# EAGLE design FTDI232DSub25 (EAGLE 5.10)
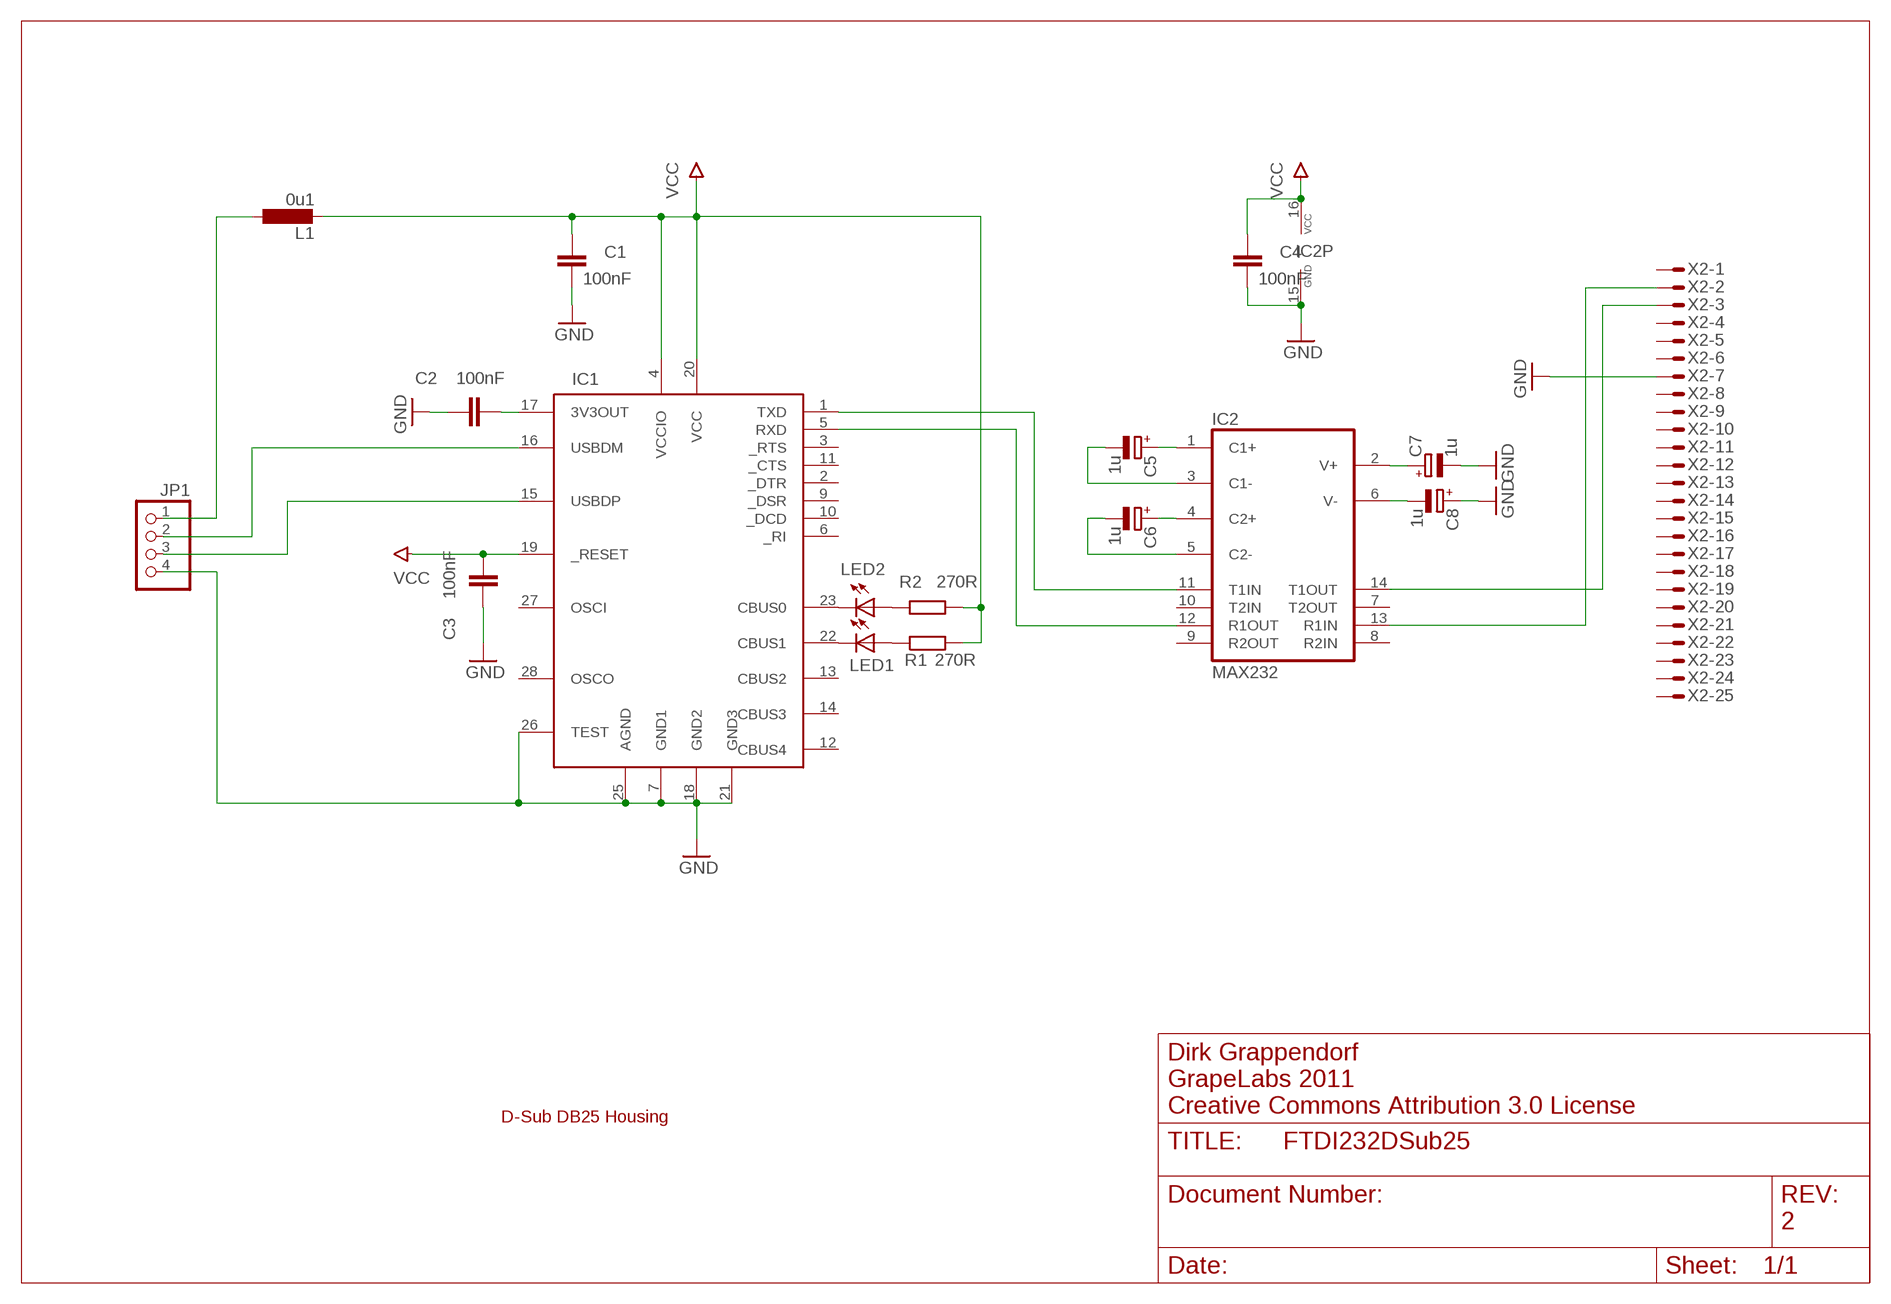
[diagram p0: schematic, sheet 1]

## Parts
C1  100nF  C-EUC1206  [C1206]
C2  100nF  C-EUC1206  [C1206]
C3  100nF  C-EUC1206  [C1206]
C4  100nF  C-EUC1206  [C1206]
C5  1u  CPOL-EUB  [PANASONIC_B]
C6  1u  CPOL-EUB  [PANASONIC_B]
C7  1u  CPOL-EUB  [PANASONIC_B]
C8  1u  CPOL-EUB  [PANASONIC_B]
IC1  FT232RL  [SSOP28DB]
IC2  MAX232  [DIL16]
JP1  PINHD-1X4  [1X04]
L1  0u1  L-EUL2825P  [L2825P]
LED1  LED3MM  [LED3MM]
LED2  LED3MM  [LED3MM]
R1  270R  R-EU_M1206  [M1206]
R2  270R  R-EU_M1206  [M1206]
U$1  DSUB25-HOUSING  [DSUB25-HOUSING]
X2  M25DS  [M25D]

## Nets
GND: C1.2 C2.1 C3.1 C4.2 C7.- C8.+ IC1.7(GND1) IC1.18(GND2) IC1.21(GND3) IC1.25(AGND) IC1.26(TEST) IC2.15(GND) JP1.4 X2.7
N$1: C2.2 IC1.17(3V3OUT)
N$2: JP1.1 L1.1
N$3: IC1.15(USBDP) JP1.3
N$4: IC1.16(USBDM) JP1.2
N$5: LED1.A R1.1
N$6: LED2.A R2.1
N$7: IC1.22(CBUS1) LED1.K(C)
N$8: IC1.23(CBUS0) LED2.K(C)
N$11: C5.+ IC2.1(C1+)
N$12: C5.- IC2.3(C1-)
N$13: C6.+ IC2.4(C2+)
N$14: C6.- IC2.5(C2-)
N$15: C7.+ IC2.2(V+)
N$16: C8.- IC2.6(V-)
N$17: IC1.1(TXD) IC2.11(T1IN)
N$18: IC2.14(T1OUT) X2.3
N$19: IC2.13(R1IN) X2.2
N$20: IC1.5(RXD) IC2.12(R1OUT)
VCC: C1.1 C3.2 C4.1 IC1.4(VCCIO) IC1.19(_RESET) IC1.20(VCC) IC2.16(VCC) L1.2 R1.2 R2.2
Unconnected: IC1.2(_DTR) IC1.3(_RTS) IC1.6(_RI) IC1.9(_DSR) IC1.10(_DCD) IC1.11(_CTS) IC1.12(CBUS4) IC1.13(CBUS2) IC1.14(CBUS3) IC1.27(OSCI) IC1.28(OSCO) IC2.7(T2OUT) IC2.8(R2IN) IC2.9(R2OUT) IC2.10(T2IN) X2.1 X2.4 X2.5 X2.6 X2.8 X2.9 X2.10 X2.11 X2.12 X2.13 X2.14 X2.15 X2.16 X2.17 X2.18 X2.19 X2.20 X2.21 X2.22 X2.23 X2.24 X2.25

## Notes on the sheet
- TxD
- RxD
- Clk6
- Clk12
- Dirk Grappendorf
- GrapeLabs 2011
- Creative Commons Attribution 3.0 License
- 2

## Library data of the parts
C1-C4 = rcl:C-EU: CAPACITOR, European symbol
C5-C8 = rcl:CPOL-EU: POLARIZED CAPACITOR, European symbol
IC1 = ftdichip:FT232RL: USB UART 4th Generation USB UART (USB <-> Serial) Controller
IC2 = maxim:MAX232: RS232 TRANSEIVER
JP1 = pinhead:PINHD-1X4: PIN HEADER
L1 = rcl:L-EU: INDUCTOR, European symbol
LED1 LED2 = led:LED: LED
R1 R2 = rcl:R-EU_: RESISTOR, European symbol
U$1 = grapelabs:DSUB25-HOUSING: Passend für 25pol D-Sub Steckergehäuse
X2 = con-subd:M25?S: SUB-D

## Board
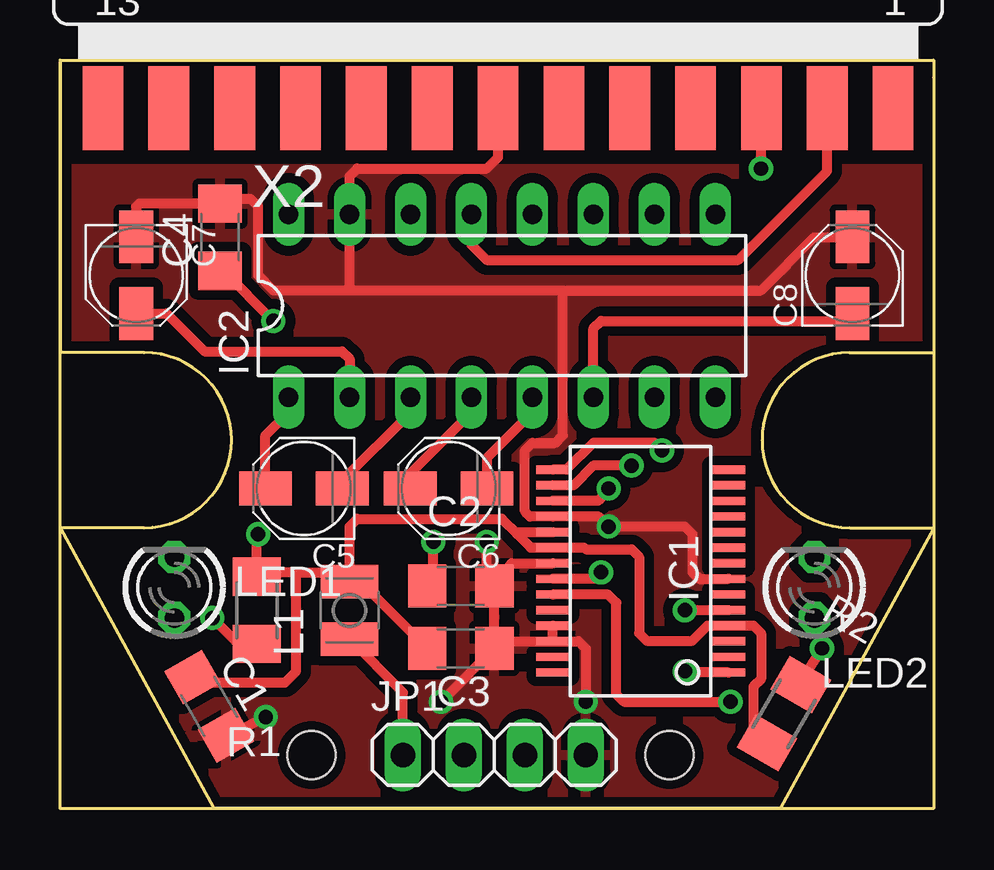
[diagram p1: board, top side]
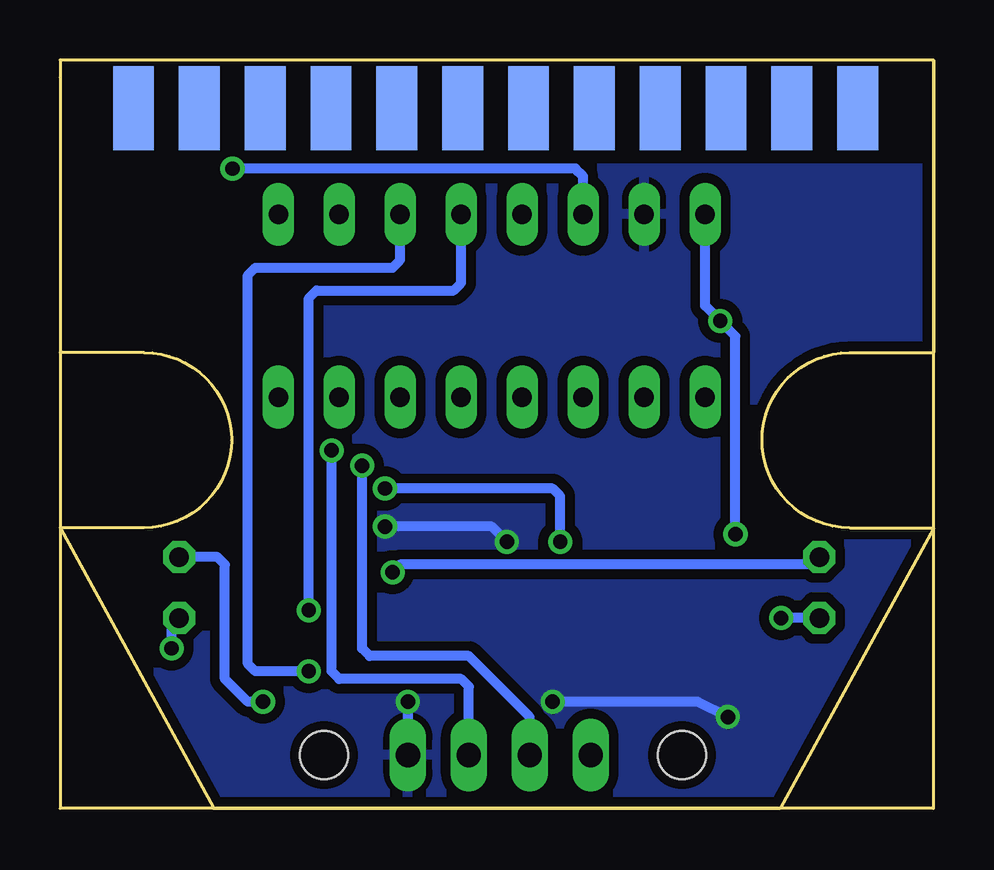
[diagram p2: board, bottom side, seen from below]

Size 36.4 x 31.2 mm. Coordinates in mm from the lower left corner, seen from the top.
Outline: 0,31.11 0,0 36.4,0 36.4,30.48
Copper layers (1*16): Top 0.035mm / dielectric 1.5mm / Bottom 0.035mm
Design rules "default *": minimum track width 10mil, minimum drill 16mil, track to track 8mil, track to pad 8mil, pad to pad 8mil, via to via 8mil, smd to smd 8mil, copper to edge 16mil, drill to drill 10mil, minimum pad ring 10mil, minimum via ring 8mil, stop-mask expansion 4mil, vias tented up to drill 0mil, thermal gap 10mil
Holes 2 mm at 10.48,2.22 25.4,2.22

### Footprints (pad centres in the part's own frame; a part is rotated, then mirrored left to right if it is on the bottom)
C1206 = smd 1.6 x 1.8: 1 -1.4,0; 2 1.4,0
PANASONIC_B = smd 2.2 x 1.4: + 1.6,0; - -1.6,0
SSOP28DB = smd 0.348 x 1.397: 1 -4.225,-3.656; 2 -3.575,-3.656; 3 -2.925,-3.656; 4 -2.275,-3.656; 5 -1.625,-3.656; 6 -0.975,-3.656; 7 -0.325,-3.656; 8 0.325,-3.656; 9 0.975,-3.656; 10 1.625,-3.656; 11 2.275,-3.656; 12 2.925,-3.656; 13 3.575,-3.656; 14 4.225,-3.656; 15 4.225,3.656; 16 3.575,3.656; 17 2.925,3.656; 18 2.275,3.656; 19 1.625,3.656; 20 0.975,3.656; 21 0.325,3.656; 22 -0.325,3.656; 23 -0.975,3.656; 24 -1.625,3.656; 25 -2.275,3.656; 26 -2.925,3.656; 27 -3.575,3.656; 28 -4.225,3.656
DIL16 = drill 0.813 long: 1 -8.89,-3.81; 2 -6.35,-3.81; 3 -3.81,-3.81; 4 -1.27,-3.81; 5 1.27,-3.81; 6 3.81,-3.81; 7 6.35,-3.81; 8 8.89,-3.81; 9 8.89,3.81; 10 6.35,3.81; 11 3.81,3.81; 12 1.27,3.81; 13 -1.27,3.81; 14 -3.81,3.81; 15 -6.35,3.81; 16 -8.89,3.81
1X04 = drill 1.016 long: 1 -3.81,0; 2 -1.27,0; 3 1.27,0; 4 3.81,0
L2825P = smd 1.4 x 2.4: 1 -1.2,0; 2 1.2,0
LED3MM = drill 0.813 octagon: A -1.27,0; K 1.27,0
M1206 = smd 1.6 x 2: 1 -1.4,0; 2 1.4,0
M25D = smd 1.7 x 3.5: 1 16.459,-6.045; 2 13.716,-6.045; 3 10.973,-6.045; 4 8.23,-6.045; 5 5.486,-6.045; 6 2.743,-6.045; 7 0,-6.045; 8 -2.743,-6.045; 9 -5.486,-6.045; 10 -8.23,-6.045; 11 -10.973,-6.045; 12 -13.716,-6.045; 13 -16.459,-6.045 | smd 1.7 x 3.5 bottom: 14 15.088,-6.045; 15 12.344,-6.045; 16 9.601,-6.045; 17 6.858,-6.045; 18 4.115,-6.045; 19 1.372,-6.045; 20 -1.372,-6.045; 21 -4.115,-6.045; 22 -6.858,-6.045; 23 -9.601,-6.045; 24 -12.344,-6.045; 25 -15.088,-6.045

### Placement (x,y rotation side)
C1  6.22,4.26 300 top
C2  16.7,9.27 180 top
C3  16.7,6.67 180 top
C4  6.67,23.81 90 top
C5  10.16,13.34 180 top
C6  16.19,13.34 180 top
C7  3.17,22.23 270 top
C8  33.02,22.23 90 top
IC1  24.19,9.89 90 top
IC2  18.41,20.95 0 top
JP1  18.1,2.22 0 top
L1  12.06,8.26 90 top
LED1  4.76,9.21 90 top
LED2  31.43,9.21 90 top
R1  8.21,8.26 90 top
R2  30.16,3.94 240 top
U$1  0,0 0 top
X2  18.25,35.23 0 top

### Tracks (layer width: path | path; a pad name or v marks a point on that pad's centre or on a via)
GND  (via drill 0.6)
  Top 0.406: IC1.21 18.81,10.22 C2.1 | C7.- 3.17,25.08 3.31,25.21 C4.2 6.86,25.4 7.94,25.4 8.26,25.08 8.26,22.23 8.89,21.59 12.06,21.59 | 20.95,21.59 12.06,21.59 | 20.95,21.59 29.21,21.59 31.43,23.81 33.01,23.81 C8.+ | 20.95,21.59 20.95,15.56 20.64,15.24 19.68,15.24 19.37,14.92 19.37,12.38 19.58,12.17 IC1.18 22.44,12.17 v22.86,11.75 26.04,11.75 26.35,11.43 26.35,9.84 26.63,9.57 IC1.7 | 12.06,21.59 IC2.15 12.06,26.35 12.38,26.67 17.78,26.67 18.25,27.14 X2.7 | C3.1 C2.1 | IC1.26 21.61,6.97 21.91,6.67 v21.91,4.45 | IC1.26 IC1.25 | IC1.26 18.4,6.97 C3.1 | C3.1 v15.88,4.45 | v8.57,3.81 7.3,3.17 6.73,2.86 C1.2 | v17.78,11.11 17.78,9.59 C2.1
  Bottom 0.406: v21.91,4.45 JP1.4 | v15.88,4.45 9.84,4.45 v8.57,3.81 | v22.86,11.75 18.41,11.75 v17.78,11.11
  pour Top (isolate 0.406): -1.27,-1.27 -1.27,26.67 37.47,26.67 37.47,-1.27
  pour Bottom (isolate 0.406): -1.27,-1.27 -1.27,26.67 37.47,26.67 37.47,-1.27
N$1  (via drill 0.6)
  Top 0.406: IC1.17 22.43,12.82 v22.86,13.34 | v15.56,11.11 15.56,9.53 C2.2
  Bottom 0.406: v22.86,13.34 15.88,13.34 15.56,13.02 v15.56,11.11
N$2
  Top 0.406: JP1.1 14.29,4.83 L1.1
N$3  (via drill 0.6)
  Top 0.406: IC1.15 21.1,14.12 22.23,15.24 24.77,15.24 v25.08,14.92
  Bottom 0.406: v25.08,14.92 25.08,5.71 24.77,5.4 19.68,5.4 19.37,5.08 JP1.3
N$4  (via drill 0.6)
  Top 0.406: IC1.16 21.41,13.47 22.23,14.29 v23.81,14.29
  Bottom 0.406: v23.81,14.29 23.81,6.67 23.5,6.35 19.37,6.35 16.83,3.81 JP1.2
N$5  (via drill 0.6)
  Top 0.406: R1.1 7.43,6.86 v6.35,7.94
  Bottom 0.406: LED1.A v6.35,7.94
N$6  (via drill 0.6)
  Top 0.406: R2.1 31.18,5.78 v31.75,6.67
  Bottom 0.406: v31.75,6.67 31.75,7.62 LED2.A
N$7  (via drill 0.6)
  Top 0.406: IC1.22 22.27,9.57 v22.54,9.84
  Bottom 0.406: v22.54,9.84 22.23,10.16 5.08,10.16 LED1.K
N$8  (via drill 0.6)
  Top 0.406: IC1.23 22.83,8.92 23.18,8.57 23.18,4.76 23.5,4.45 v27.94,4.45
  Bottom 0.406: v27.94,4.45 28.57,4.45 29.53,5.4 29.53,10.16 29.84,10.48 LED2.K
N$11
  Top 0.406: C5.+ 8.56,15.54 9.53,16.51 IC2.1
N$12
  Top 0.406: C5.- 11.76,13.66 14.61,16.51 IC2.3
N$13
  Top 0.406: C6.+ 14.59,13.96 17.14,16.51 IC2.4
N$14
  Top 0.406: C6.- 17.79,14.62 19.68,16.51 IC2.5
N$15
  Top 0.406: IC2.2 12.06,18.73 11.75,19.05 6.03,19.05 4.45,20.64 3.19,20.64 C7.+
N$16
  Top 0.406: IC2.6 22.23,20 22.54,20.32 32.72,20.32 C8.-
N$17  (via drill 0.6)
  Top 0.406: IC1.1 26.4,5.67 v26.04,5.71
  Bottom 0.406: v26.04,5.71 28.26,5.71 28.57,6.03 28.57,22.23 28.26,22.54 22.54,22.54 22.23,22.86 IC2.11
N$18  (via drill 0.6)
  Top 0.406: v29.21,26.67 29.21,29.17 X2.3
  Bottom 0.406: IC2.14 14.61,26.35 14.92,26.67 v29.21,26.67
N$19
  Top 0.406: IC2.13 17.14,23.5 17.78,22.86 28.26,22.86 31.97,26.57 X2.2
N$20  (via drill 0.6)
  Top 0.406: v26.04,8.26 27.84,8.26 IC1.5
  Bottom 0.406: IC2.12 19.68,21.91 20,21.59 25.72,21.59 26.04,21.27 v26.04,8.26
VCC  (via drill 0.6)
  Top 0.406: 19.05,11.43 18.41,12.06 12.38,12.06 12.06,11.75 L1.2 | 19.05,11.43 19.61,10.87 IC1.20 21.84,10.87 21.91,10.79 23.81,10.79 24.13,10.48 24.13,7.3 24.45,6.99 26.35,6.99 26.99,7.62 IC1.4 28.89,7.62 29.21,7.3 29.21,5.4 28.89,5.08 28.89,3.3 R2.2 29.21,3.3 | IC1.19 19.14,11.52 19.05,11.43 | 9.84,9.84 8.26,9.84 8.26,9.65 R1.2 8.21,11.38 v8.26,11.43 | 9.84,9.84 11.68,9.84 L1.2 | 9.84,9.84 9.84,5.71 9.38,5.25 5.74,5.25 C1.1 | L1.2 12.51,9.46 C3.2 | C4.1 6.8,22.41 v8.89,20.32
  Bottom 0.406: v8.26,11.43 8.26,19.68 v8.89,20.32 9.53,20.95 IC2.16

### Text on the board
bohr: 24,013 | 13,335 | 12.065 | 18,0975 | 9,525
